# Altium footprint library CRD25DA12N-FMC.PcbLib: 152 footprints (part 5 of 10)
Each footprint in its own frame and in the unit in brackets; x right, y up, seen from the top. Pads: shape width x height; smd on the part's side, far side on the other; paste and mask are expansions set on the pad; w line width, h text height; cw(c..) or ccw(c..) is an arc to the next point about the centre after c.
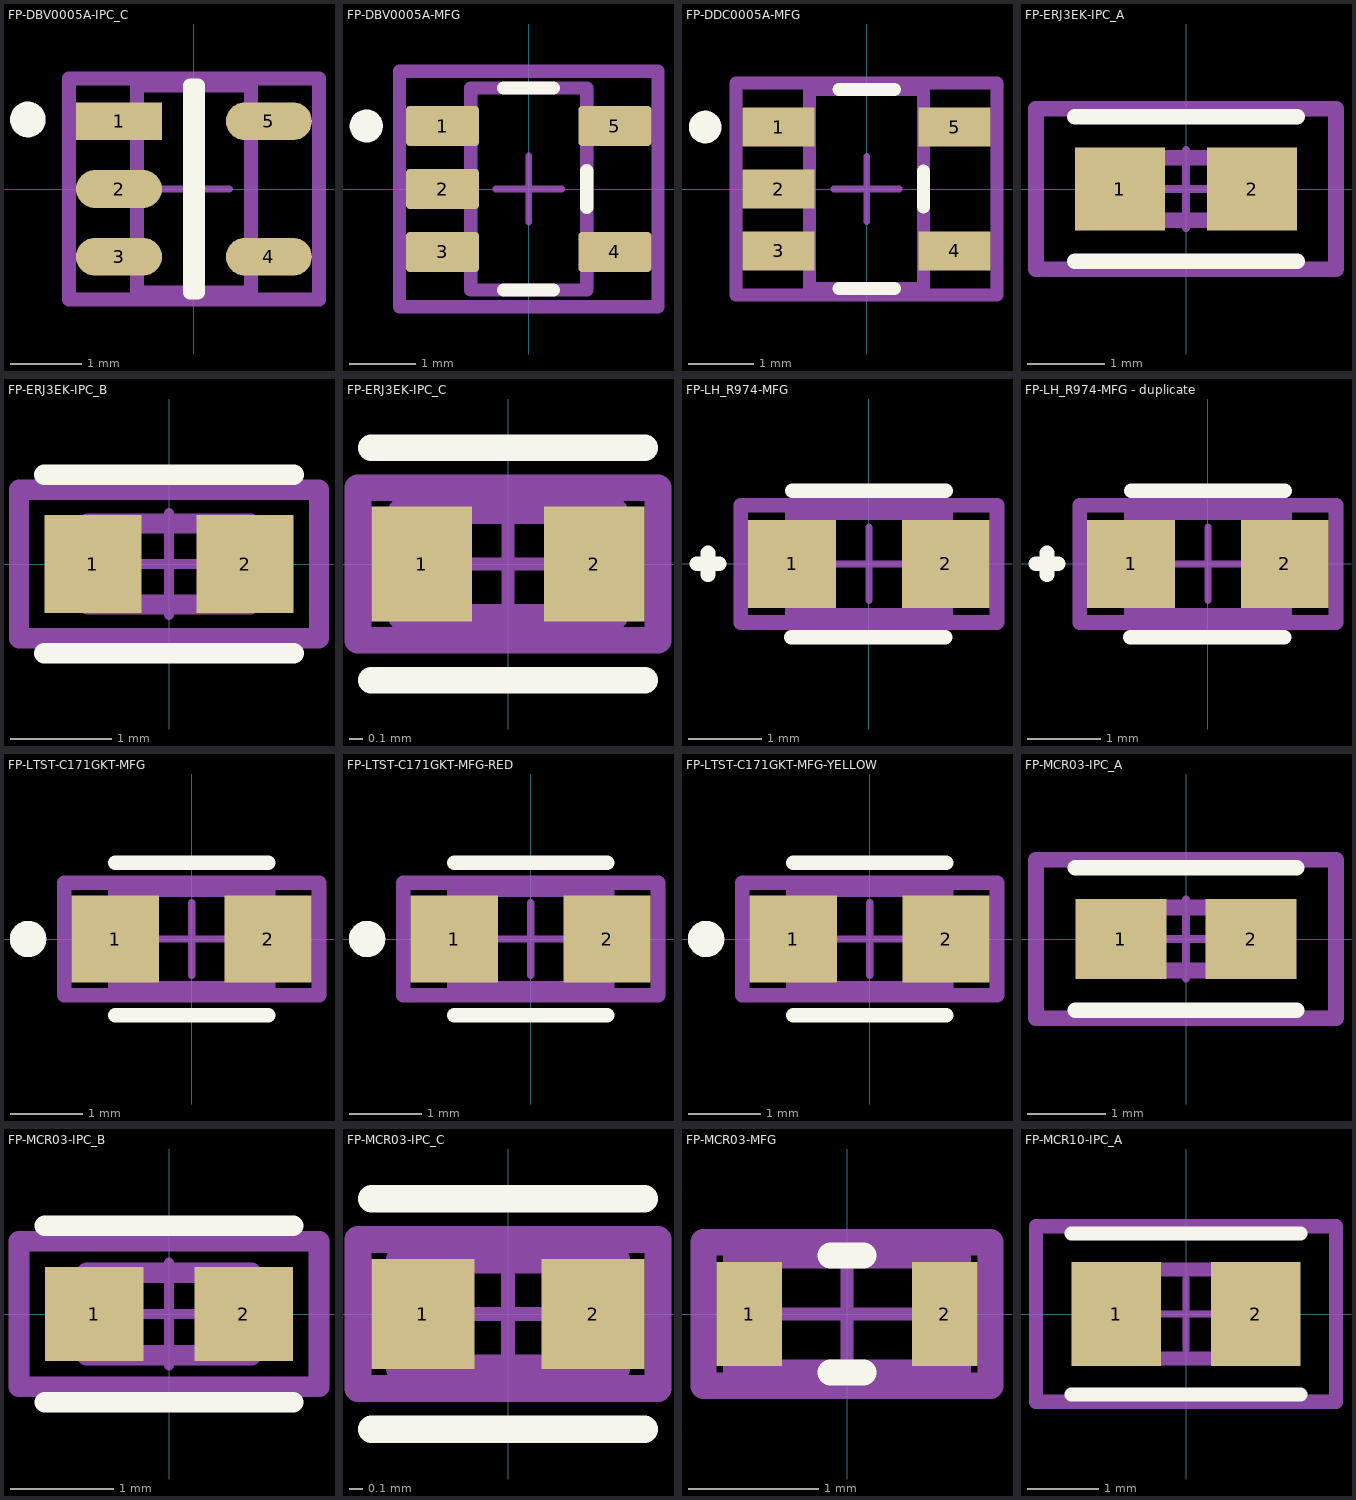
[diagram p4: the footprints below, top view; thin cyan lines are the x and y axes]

## FP-DBV0005A-IPC_C [mm]
pads (5):
  rect 1.205x0.532 smd paste+0 mask+0: 1(-1.05,0.95)
  rrect100% 1.205x0.532 smd paste+0 mask+0: 2(-1.05,0) 3(-1.05,-0.95) 4(1.05,-0.95) 5(1.05,0.95)
Top Overlay:
  circle w0.25: c-2.328,0.975 r0.125
  lines w0.2: -0.052,-1.45 -0.052,1.45 0.052,1.45 0.052,-1.45 -0.052,-1.45
Mechanical 5:
  lines w0.2: -1.753,-1.55 1.753,-1.55 1.753,1.55 -1.753,1.55 -1.753,-1.55
  text ".Designator" at 0,0.188 h1
Mechanical 13:
  lines w0.2: -0.8,-1.45 0.8,-1.45 0.8,1.45 -0.8,1.45 -0.8,-1.45
Mechanical 15:
  lines w0.2: -1.753,-1.55 1.753,-1.55 1.753,1.55 -1.753,1.55 -1.753,-1.55
Mechanical 16:
  lines w0.1: -0.5,0 0.5,0 ; 0,-0.5 0,0.5
3D body "IC_Texas_Instruments_SN74AHC1G00DBVR_eec.STEP": height 0.25, standoff 0, extent -1.753,-1.55 1.753,1.55

## FP-DBV0005A-MFG [mm]
pads (5):
  rrect17% 1.1x0.6 smd paste+0 mask+0: 1(-1.3,0.95) 2(-1.3,0) 3(-1.3,-0.95) 4(1.3,-0.95) 5(1.3,0.95)
Top Overlay:
  circle w0.25: c-2.45,0.95 r0.125
  lines w0.2: -0.375,-1.525 0.375,-1.525 ; -0.375,1.525 0.375,1.525 ; 0.875,-0.275 0.875,0.275
Mechanical 5:
  lines w0.2: -1.95,-1.775 1.95,-1.775 1.95,1.775 -1.95,1.775 -1.95,-1.775
  text ".Designator" at 0,0 h1
Mechanical 13:
  lines w0.2: -0.875,-1.525 0.875,-1.525 0.875,1.525 -0.875,1.525 -0.875,-1.525
Mechanical 15:
  lines w0.2: -1.95,-1.775 1.95,-1.775 1.95,1.775 -1.95,1.775 -1.95,-1.775
Mechanical 16:
  lines w0.1: -0.5,0 0.5,0 ; 0,-0.5 0,0.5
3D body "IC_Texas_Instruments_SN65LVDT2DBVT_eec.STEP": height 0.25, standoff 0, extent -1.95,-1.775 1.95,1.775

## FP-DDC0005A-MFG [mm]
pads (5):
  rect 1.1x0.6 smd paste+0 mask+0: 1(-1.35,0.95) 2(-1.35,0) 3(-1.35,-0.95) 4(1.35,-0.95) 5(1.35,0.95)
Top Overlay:
  circle w0.25: c-2.475,0.95 r0.125
  lines w0.2: -0.425,-1.525 0.425,-1.525 ; -0.425,1.525 0.425,1.525 ; 0.875,-0.275 0.875,0.275
Mechanical 5:
  lines w0.2: -2,-1.625 -2,1.625 2,1.625 2,-1.625 -2,-1.625
  text ".Designator" at 0,0 h1
Mechanical 13:
  lines w0.2: -0.875,-1.525 -0.875,1.525 0.875,1.525 0.875,-1.525 -0.875,-1.525
Mechanical 15:
  lines w0.2: -2,-1.625 -2,1.625 2,1.625 2,-1.625 -2,-1.625
Mechanical 16:
  lines w0.1: -0.5,0 0.5,0 ; 0,-0.5 0,0.5
3D body "IC_Texas_Instruments_TPS62561DDCT_eec.STEP": height 0.25, standoff 0, extent -2,-1.625 2,1.625

## FP-ERJ3EK-IPC_A [mil]
pads (2):
  rect 45.53x41.82 smd paste+0 mask+0: 1(-33.5,0) 2(33.5,0)
Top Overlay:
  lines w7.87: -56.26,-36.66 56.26,-36.66 ; -56.26,36.66 56.26,36.66
Mechanical 5:
  lines w7.87: -75.95,-40.59 75.95,-40.59 75.95,40.59 -75.95,40.59 -75.95,-40.59
  text ".Designator" at 0,7.4 h39.37
Mechanical 13:
  lines w7.87: -31.5,-15.75 31.5,-15.75 31.5,15.75 -31.5,15.75 -31.5,-15.75
Mechanical 15:
  lines w7.87: -75.95,-40.59 75.95,-40.59 75.95,40.59 -75.95,40.59 -75.95,-40.59
Mechanical 16:
  lines w3.94: -19.68,0 19.68,0 ; 0,-19.68 0,19.68
3D body "Res_Panasonic_ERJ-3EKF12R0V_eec.STEP": height 10, standoff 0, extent -75.95,-40.59 75.95,40.59

## FP-ERJ3EK-IPC_B [mm]
pads (2):
  rect 0.957x0.962 smd paste+0 mask+0: 1(-0.751,0) 2(0.751,0)
Top Overlay:
  lines w0.2: -1.229,-0.881 1.229,-0.881 ; -1.229,0.881 1.229,0.881
Mechanical 5:
  lines w0.2: -1.479,-0.731 1.479,-0.731 1.479,0.731 -1.479,0.731 -1.479,-0.731
  text ".Designator" at 0,0.188 h1
Mechanical 13:
  lines w0.2: -0.8,-0.4 0.8,-0.4 0.8,0.4 -0.8,0.4 -0.8,-0.4
Mechanical 15:
  lines w0.2: -1.479,-0.731 1.479,-0.731 1.479,0.731 -1.479,0.731 -1.479,-0.731
Mechanical 16:
  lines w0.1: -0.5,0 0.5,0 ; 0,-0.5 0,0.5
3D body "Res_Panasonic_ERJ-3EKF12R0V_eec.STEP": height 0.25, standoff 0, extent -1.479,-0.731 1.479,0.731

## FP-ERJ3EK-IPC_C [mm]
pads (2):
  rect 0.757x0.862 smd paste+0 mask+0: 1(-0.651,0) 2(0.651,0)
Top Overlay:
  lines w0.2: -1.029,-0.875 1.029,-0.875 ; -1.029,0.875 1.029,0.875
Mechanical 5:
  lines w0.2: -1.129,-0.575 1.129,-0.575 1.129,0.575 -1.129,0.575 -1.129,-0.575
  text ".Designator" at 0,0.188 h1
Mechanical 13:
  lines w0.2: -0.8,-0.4 0.8,-0.4 0.8,0.4 -0.8,0.4 -0.8,-0.4
Mechanical 15:
  lines w0.2: -1.129,-0.575 1.129,-0.575 1.129,0.575 -1.129,0.575 -1.129,-0.575
Mechanical 16:
  lines w0.1: -0.5,0 0.5,0 ; 0,-0.5 0,0.5
3D body "Res_Panasonic_ERJ-3EKF12R0V_eec.STEP": height 0.25, standoff 0, extent -1.129,-0.575 1.129,0.575

## FP-LH_R974-MFG [mm]
pads (2):
  rect 1.2x1.2 smd paste+0 mask+0: 1(-1.05,0) 2(1.05,0)
Top Overlay:
  lines w0.2: -2.35,0 -2.05,0 ; -2.2,-0.15 -2.2,0.15 ; -1.061,-1.002 1.039,-1.002 ; -1.05,1 1.05,1
Mechanical 5:
  lines w0.2: -1.75,-0.8 1.75,-0.8 1.75,0.8 -1.75,0.8 -1.75,-0.8
  text ".Designator" at 0,0 h1
Mechanical 13:
  lines w0.2: -1.05,-0.7 1.05,-0.7 1.05,0.7 -1.05,0.7 -1.05,-0.7
Mechanical 15:
  lines w0.2: -1.75,-0.8 1.75,-0.8 1.75,0.8 -1.75,0.8 -1.75,-0.8
Mechanical 16:
  lines w0.1: -0.5,0 0.5,0 ; 0,-0.5 0,0.5
3D body "Diode_OSRAM_LH_R974-LP-1_eec.STEP": height 0.25, standoff 0, extent -1.75,-0.8 1.75,0.8

## FP-LH_R974-MFG - duplicate [mm]
pads (2):
  rect 1.2x1.2 smd paste+0 mask+0: 1(-1.05,0) 2(1.05,0)
Top Overlay:
  lines w0.2: -2.35,0 -2.05,0 ; -2.2,-0.15 -2.2,0.15 ; -1.061,-1.002 1.039,-1.002 ; -1.05,1 1.05,1
Mechanical 5:
  lines w0.2: -1.75,-0.8 1.75,-0.8 1.75,0.8 -1.75,0.8 -1.75,-0.8
  text ".Designator" at 0,0 h1
Mechanical 13:
  lines w0.2: -1.05,-0.7 1.05,-0.7 1.05,0.7 -1.05,0.7 -1.05,-0.7
Mechanical 15:
  lines w0.2: -1.75,-0.8 1.75,-0.8 1.75,0.8 -1.75,0.8 -1.75,-0.8
Mechanical 16:
  lines w0.1: -0.5,0 0.5,0 ; 0,-0.5 0,0.5
3D body "Diode_OSRAM_LH_R974-LP-1_eec.STEP": height 0.25, standoff 0, extent -1.75,-0.8 1.75,0.8

## FP-LTST-C171GKT-MFG [mm]
pads (2):
  rect 1.2x1.2 smd paste+0 mask+0: 1(-1.05,0) 2(1.05,0)
Top Overlay:
  circle w0.25: c-2.25,0 r0.125
  lines w0.2: -1.05,-1.05 1.05,-1.05 ; -1.05,1.05 1.05,1.05
Mechanical 5:
  lines w0.2: -1.75,-0.775 -1.75,0.775 1.75,0.775 1.75,-0.775 -1.75,-0.775
  text ".Designator" at 0,0 h1
Mechanical 13:
  lines w0.2: -1.05,-0.675 -1.05,0.675 1.05,0.675 1.05,-0.675 -1.05,-0.675
Mechanical 15:
  lines w0.2: -1.75,-0.775 -1.75,0.775 1.75,0.775 1.75,-0.775 -1.75,-0.775
Mechanical 16:
  lines w0.1: -0.5,0 0.5,0 ; 0,-0.5 0,0.5
3D body "Diode_Lite-On_LTST-C171GKT_eec.STEP": height 0.25, standoff 0, extent -1.75,-0.775 1.75,0.775

## FP-LTST-C171GKT-MFG-RED [mm]
pads (2):
  rect 1.2x1.2 smd paste+0 mask+0: 1(-1.05,0) 2(1.05,0)
Top Overlay:
  circle w0.25: c-2.25,0 r0.125
  lines w0.2: -1.05,-1.05 1.05,-1.05 ; -1.05,1.05 1.05,1.05
Mechanical 5:
  lines w0.2: -1.75,-0.775 -1.75,0.775 1.75,0.775 1.75,-0.775 -1.75,-0.775
  text ".Designator" at 0,0 h1
Mechanical 13:
  lines w0.2: -1.05,-0.675 -1.05,0.675 1.05,0.675 1.05,-0.675 -1.05,-0.675
Mechanical 15:
  lines w0.2: -1.75,-0.775 -1.75,0.775 1.75,0.775 1.75,-0.775 -1.75,-0.775
Mechanical 16:
  lines w0.1: -0.5,0 0.5,0 ; 0,-0.5 0,0.5
3D body "LED 0805 - RED.STEP": height 0.8, standoff 0, extent -1,-0.625 1,0.625

## FP-LTST-C171GKT-MFG-YELLOW [mm]
pads (2):
  rect 1.2x1.2 smd paste+0 mask+0: 1(-1.05,0) 2(1.05,0)
Top Overlay:
  circle w0.25: c-2.25,0 r0.125
  lines w0.2: -1.05,-1.05 1.05,-1.05 ; -1.05,1.05 1.05,1.05
Mechanical 5:
  lines w0.2: -1.75,-0.775 1.75,-0.775 1.75,0.775 -1.75,0.775 -1.75,-0.775
  text ".Designator" at 0,0 h1
Mechanical 13:
  lines w0.2: -1.05,-0.675 1.05,-0.675 1.05,0.675 -1.05,0.675 -1.05,-0.675
Mechanical 15:
  lines w0.2: -1.75,-0.775 1.75,-0.775 1.75,0.775 -1.75,0.775 -1.75,-0.775
Mechanical 16:
  lines w0.1: -0.5,0 0.5,0 ; 0,-0.5 0,0.5
3D body "LED 0805 - YELLOW.STEP": height 0.8, standoff 0, extent -1,-0.625 1,0.625

## FP-MCR03-IPC_A [mm]
pads (2):
  rect 1.158x1.012 smd paste+0 mask+0: 1(-0.827,0) 2(0.827,0)
Top Overlay:
  lines w0.2: -1.406,-0.906 1.406,-0.906 ; -1.406,0.906 1.406,0.906
Mechanical 5:
  lines w0.2: -1.906,-1.006 -1.906,1.006 1.906,1.006 1.906,-1.006 -1.906,-1.006
  text ".Designator" at 0,0.188 h1
Mechanical 13:
  lines w0.2: -0.8,-0.4 -0.8,0.4 0.8,0.4 0.8,-0.4 -0.8,-0.4
Mechanical 15:
  lines w0.2: -1.906,-1.006 -1.906,1.006 1.906,1.006 1.906,-1.006 -1.906,-1.006
Mechanical 16:
  lines w0.1: -0.5,0 0.5,0 ; 0,-0.5 0,0.5
3D body "Res_Rohm_MCR03ERTF1182_eec.STEP": height 0.25, standoff 0, extent -1.906,-1.006 1.906,1.006

## FP-MCR03-IPC_B [mm]
pads (2):
  rect 0.958x0.912 smd paste+0 mask+0: 1(-0.727,0) 2(0.727,0)
Top Overlay:
  lines w0.2: -1.206,-0.856 1.206,-0.856 ; -1.206,0.856 1.206,0.856
Mechanical 5:
  lines w0.2: -1.456,-0.706 1.456,-0.706 1.456,0.706 -1.456,0.706 -1.456,-0.706
  text ".Designator" at 0,0.188 h1
Mechanical 13:
  lines w0.2: -0.8,-0.4 0.8,-0.4 0.8,0.4 -0.8,0.4 -0.8,-0.4
Mechanical 15:
  lines w0.2: -1.456,-0.706 1.456,-0.706 1.456,0.706 -1.456,0.706 -1.456,-0.706
Mechanical 16:
  lines w0.1: -0.5,0 0.5,0 ; 0,-0.5 0,0.5
3D body "Res_Rohm_MCR03ERTF1182_eec.STEP": height 0.25, standoff 0, extent -1.456,-0.706 1.456,0.706

## FP-MCR03-IPC_C [mm]
pads (2):
  rect 0.758x0.812 smd paste+0 mask+0: 1(-0.627,0) 2(0.627,0)
Top Overlay:
  lines w0.2: -1.006,-0.85 1.006,-0.85 ; -1.006,0.85 1.006,0.85
Mechanical 5:
  lines w0.2: -1.106,-0.55 1.106,-0.55 1.106,0.55 -1.106,0.55 -1.106,-0.55
  text ".Designator" at 0,0.188 h1
Mechanical 13:
  lines w0.2: -0.8,-0.4 0.8,-0.4 0.8,0.4 -0.8,0.4 -0.8,-0.4
Mechanical 15:
  lines w0.2: -1.106,-0.55 1.106,-0.55 1.106,0.55 -1.106,0.55 -1.106,-0.55
Mechanical 16:
  lines w0.1: -0.5,0 0.5,0 ; 0,-0.5 0,0.5
3D body "Res_Rohm_MCR03ERTF1182_eec.STEP": height 0.25, standoff 0, extent -1.106,-0.55 1.106,0.55

## FP-MCR03-MFG [mm]
pads (2):
  rect 0.5x0.8 smd paste+0 mask+0: 1(-0.75,0) 2(0.75,0)
Top Overlay:
  lines w0.2: -0.125,-0.45 0.125,-0.45 ; -0.125,0.45 0.125,0.45
Mechanical 5:
  lines w0.2: -1.1,-0.55 -1.1,0.55 1.1,0.55 1.1,-0.55 -1.1,-0.55
  text ".Designator" at 0,0.188 h1
Mechanical 13:
  lines w0.2: -0.85,-0.45 -0.85,0.45 0.85,0.45 0.85,-0.45 -0.85,-0.45
Mechanical 15:
  lines w0.2: -1.1,-0.55 -1.1,0.55 1.1,0.55 1.1,-0.55 -1.1,-0.55
Mechanical 16:
  lines w0.1: -0.5,0 0.5,0 ; 0,-0.5 0,0.5
3D body "Res_Rohm_MCR03ERTF1182_eec.STEP": height 0.25, standoff 0, extent -1.1,-0.55 1.1,0.55

## FP-MCR10-IPC_A [mm]
pads (2):
  rect 1.258x1.462 smd paste+0 mask+0: 1(-0.977,0) 2(0.977,0)
Top Overlay:
  lines w0.2: -1.606,-1.131 1.606,-1.131 ; -1.606,1.131 1.606,1.131
Mechanical 5:
  lines w0.2: -2.106,-1.231 2.106,-1.231 2.106,1.231 -2.106,1.231 -2.106,-1.231
  text ".Designator" at 0,0.188 h1
Mechanical 13:
  lines w0.2: -1,-0.625 1,-0.625 1,0.625 -1,0.625 -1,-0.625
Mechanical 15:
  lines w0.2: -2.106,-1.231 2.106,-1.231 2.106,1.231 -2.106,1.231 -2.106,-1.231
Mechanical 16:
  lines w0.1: -0.5,0 0.5,0 ; 0,-0.5 0,0.5
3D body "Res_Rohm_MCR10ERTJ510_eec.STEP": height 0.25, standoff 0, extent -2.106,-1.231 2.106,1.231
